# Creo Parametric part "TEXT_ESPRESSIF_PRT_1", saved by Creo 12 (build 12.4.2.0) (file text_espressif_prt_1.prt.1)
Units: Custom; MM, KILOGRAM, SECS

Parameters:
  PTC_WM_ITERATION = "0"
  PTC_WM_VERSION = "-.0"
  PTC_WM_LIFECYCLE_STATE = "In Work"
  PTC_WM_LIFECYCLE = "MO_CADDocument"
  PTC_WM_CREATED_BY = "Maximilian Roepper (Z0017RMS: MO)"
  PTC_WM_CREATED_ON = "18-Sep-26 11:36:42 AM"
  PTC_WM_MODIFIED_BY = "Maximilian Roepper (Z0017RMS: MO)"
  PTC_WM_MODIFIED_ON = "18-Sep-26 11:36:46 AM"
  PDMLINKNUMBER = "PDM000071455128"
  PTC_WM_NAME = "text_espressif_prt_1.prt"
  PTC_WM_NUMBER = "PDM000071455128"

Other parameters: WEIGHT, WEIGHT_FACTOR, WEIGHT_ADD, _MASS_TEMP, _DIFF_TEMP, MC_ERRORS, SUPPLIER

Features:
  1. coordinate system
  2. datum plane "PRT_YZ"
  3. datum plane "PRT_XY"
  4. datum plane "PRT_XZ"
  5. coordinate system
  6. datum axis
  7. datum axis
  8. datum axis
  9. coordinate system
  10. imported feature
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
Other named items: PRT, SIEMENS_MO, DRW_VIEW_ORG, PRT_X, PRT_Y, PRT_Z, CS0, ROUGH_GROB

Layers: 00_STD_CSYS-KSYS, 01_STD_PLANES-EBENEN, 02_STD_AXES-ACHSEN, 03_STD_CSYS-KSYS, 24_IMPORT_FEAT-IMPORT_KE

Surfaces: 14 plane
